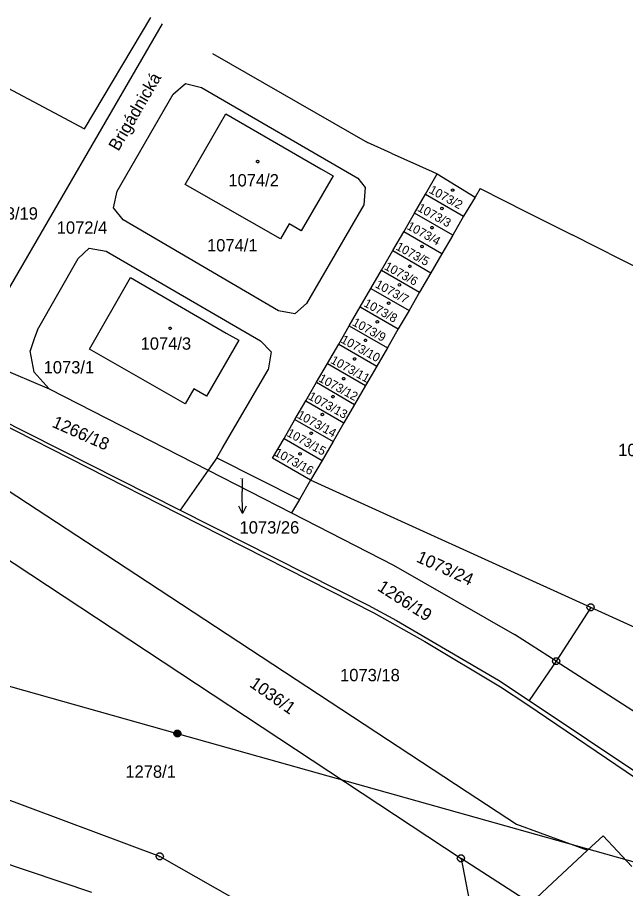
# Model space of a CAD drawing. Extents: x -806774 to -803680, y -1151731 to -1150053.
# Drawn here: x -804287.8 to -804204.1, y -1150483.9 to -1150364 of the extents above; entities that cross this region are included whole.
import ezdxf

# ---------------------------------------------------------------- set-up
doc = ezdxf.new("R2010")
doc.units = 0
for name, color, linetype in [('1', 7, 'Continuous'), ('12', 7, 'Continuous'), ('2', 7, 'Continuous'), ('5', 7, 'Continuous'), ('6', 7, 'Continuous'), ('7', 7, 'Continuous'), ('8', 7, 'Continuous')]:
    doc.layers.add(name, color=color, linetype=linetype)

msp = doc.modelspace()

# ---------------------------------------------------------------- linework, layer by layer
at = {"layer": '1'}
for p, q in [((-804290.87, -1150404.61), (-804267.79, -1150364.83)), ((-804278.54, -1150379.3), (-804269.42, -1150363.95)), ((-804298.27, -1150368.8), (-804278.54, -1150379.3)), ((-804260.94, -1150368.94), (-804239.57, -1150381.18)), ((-804266.34, -1150374.52), (-804264.66, -1150373.06)), ((-804264.66, -1150373.06), (-804262.44, -1150373.59)), ((-804262.44, -1150373.59), (-804240.91, -1150386.08)), ((-804274.06, -1150387.9), (-804266.34, -1150374.52)), ((-804264.71, -1150386.94), (-804259.1, -1150377.21)), ((-804259.1, -1150377.21), (-804246, -1150384.78)), ((-804236.34, -1150382.63), (-804239.57, -1150381.18)), ((-804236.34, -1150382.63), (-804230.68, -1150385.18)), ((-804246, -1150384.78), (-804244.3, -1150385.76)), ((-804230.68, -1150385.18), (-804230.02, -1150385.47)), ((-804244.3, -1150385.76), (-804248.7, -1150393.35)), ((-804240.91, -1150386.08), (-804239.91, -1150387.38)), ((-804231.6, -1150388.3), (-804230.02, -1150385.47)), ((-804230.02, -1150385.47), (-804224.77, -1150388.7)), ((-804251.58, -1150394.44), (-804264.71, -1150386.94)), ((-804239.91, -1150387.38), (-804240.1, -1150389.76)), ((-804224.07, -1150387.51), (-804224.77, -1150388.7)), ((-804224.07, -1150387.51), (-804217.74, -1150390.71)), ((-804274.55, -1150390.16), (-804274.06, -1150387.9)), ((-804233.1, -1150390.9), (-804231.6, -1150388.3)), ((-804231.6, -1150388.3), (-804226.36, -1150391.34)), ((-804224.77, -1150388.7), (-804226.36, -1150391.34)), ((-804240.1, -1150389.76), (-804248.01, -1150403.37)), ((-804273.23, -1150391.84), (-804274.55, -1150390.16)), ((-804234.59, -1150393.46), (-804233.1, -1150390.9)), ((-804227.86, -1150393.94), (-804233.1, -1150390.9)), ((-804217.74, -1150390.71), (-804211.44, -1150393.91)), ((-804251.86, -1150404.36), (-804273.23, -1150391.84)), ((-804250.38, -1150392.37), (-804251.58, -1150394.44)), ((-804248.7, -1150393.35), (-804250.38, -1150392.37)), ((-804226.36, -1150391.34), (-804227.86, -1150393.94)), ((-804236.1, -1150396.07), (-804234.59, -1150393.46)), ((-804229.34, -1150396.5), (-804234.59, -1150393.46)), ((-804227.86, -1150393.94), (-804229.34, -1150396.5)), ((-804193.78, -1150402.81), (-804211.44, -1150393.91)), ((-804279.4, -1150397.15), (-804277.88, -1150395.72)), ((-804277.88, -1150395.72), (-804275.56, -1150396.16)), ((-804237.66, -1150398.76), (-804236.1, -1150396.07)), ((-804236.1, -1150396.07), (-804230.86, -1150399.11)), ((-804285.02, -1150406.97), (-804279.4, -1150397.15)), ((-804275.56, -1150396.16), (-804254.32, -1150408.51)), ((-804229.34, -1150396.5), (-804230.86, -1150399.11)), ((-804239.11, -1150401.26), (-804237.66, -1150398.76)), ((-804237.66, -1150398.76), (-804232.42, -1150401.8)), ((-804230.86, -1150399.11), (-804232.42, -1150401.8)), ((-804277.84, -1150409.62), (-804272.2, -1150399.78)), ((-804272.2, -1150399.78), (-804259.06, -1150407.42)), ((-804240.59, -1150403.81), (-804239.11, -1150401.26)), ((-804239.11, -1150401.26), (-804233.87, -1150404.3)), ((-804232.42, -1150401.8), (-804233.87, -1150404.3)), ((-804249.6, -1150404.77), (-804251.86, -1150404.36)), ((-804248.01, -1150403.37), (-804249.6, -1150404.77)), ((-804242.1, -1150406.41), (-804240.59, -1150403.81)), ((-804240.59, -1150403.81), (-804235.35, -1150406.85)), ((-804233.87, -1150404.3), (-804235.35, -1150406.85)), ((-804243.56, -1150408.94), (-804242.1, -1150406.41)), ((-804242.1, -1150406.41), (-804236.85, -1150409.45)), ((-804235.35, -1150406.85), (-804236.85, -1150409.45)), ((-804285.02, -1150406.97), (-804285.45, -1150408.22)), ((-804259.06, -1150407.42), (-804257.31, -1150408.41)), ((-804285.45, -1150408.22), (-804286.03, -1150409.89)), ((-804257.31, -1150408.41), (-804261.75, -1150416.09)), ((-804254.32, -1150408.51), (-804252.87, -1150409.99)), ((-804245.11, -1150411.61), (-804243.56, -1150408.94)), ((-804243.56, -1150408.94), (-804238.32, -1150411.98)), ((-804285.45, -1150412.79), (-804286.03, -1150409.89)), ((-804264.67, -1150417.17), (-804277.84, -1150409.62)), ((-804252.87, -1150409.99), (-804253.25, -1150412.49)), ((-804236.85, -1150409.45), (-804238.32, -1150411.98)), ((-804246.61, -1150414.2), (-804245.11, -1150411.61)), ((-804245.11, -1150411.61), (-804239.87, -1150414.65)), ((-804291.43, -1150411.7), (-804283.39, -1150415.1)), ((-804283.39, -1150415.1), (-804285.45, -1150412.79)), ((-804259.59, -1150423.33), (-804253.25, -1150412.49)), ((-804238.32, -1150411.98), (-804239.87, -1150414.65)), ((-804283.39, -1150415.1), (-804261.52, -1150426.31)), ((-804263.48, -1150415.09), (-804264.67, -1150417.17)), ((-804261.75, -1150416.09), (-804263.48, -1150415.09)), ((-804248.08, -1150416.74), (-804246.61, -1150414.2)), ((-804246.61, -1150414.2), (-804241.37, -1150417.24)), ((-804239.87, -1150414.65), (-804241.37, -1150417.24)), ((-804294.74, -1150417.47), (-804265.66, -1150432.25)), ((-804294.48, -1150417.09), (-804265.36, -1150431.82)), ((-804249.58, -1150419.32), (-804248.08, -1150416.74)), ((-804248.08, -1150416.74), (-804242.84, -1150419.78)), ((-804241.37, -1150417.24), (-804242.84, -1150419.78)), ((-804251.08, -1150421.93), (-804249.58, -1150419.32)), ((-804249.58, -1150419.32), (-804244.34, -1150422.36)), ((-804242.84, -1150419.78), (-804244.34, -1150422.36)), ((-804252.65, -1150424.64), (-804251.08, -1150421.93)), ((-804251.08, -1150421.93), (-804245.85, -1150424.97)), ((-804244.34, -1150422.36), (-804245.85, -1150424.97)), ((-804298.67, -1150422.8), (-804271.5, -1150440.64)), ((-804260.34, -1150424.61), (-804259.59, -1150423.33)), ((-804260.34, -1150424.61), (-804261.52, -1150426.31)), ((-804260.34, -1150424.61), (-804248.96, -1150430.34)), ((-804247.42, -1150427.68), (-804252.65, -1150424.64)), ((-804245.85, -1150424.97), (-804247.42, -1150427.68)), ((-804261.52, -1150426.31), (-804265.36, -1150431.82)), ((-804261.52, -1150426.31), (-804250.04, -1150432.2)), ((-804247.42, -1150427.68), (-804248.96, -1150430.34)), ((-804208.87, -1150445.2), (-804247.42, -1150427.68)), ((-804301, -1150430.74), (-804226.72, -1150479.76)), ((-804248.96, -1150430.34), (-804250.04, -1150432.2)), ((-804265.36, -1150431.82), (-804239.5, -1150444.89)), ((-804265.66, -1150432.25), (-804238.71, -1150445.94)), ((-804250.04, -1150432.2), (-804236.02, -1150439.39)), ((-804236.02, -1150439.39), (-804219.37, -1150448.94)), ((-804271.5, -1150440.64), (-804225.88, -1150470.58)), ((-804239.5, -1150444.89), (-804235.62, -1150446.99)), ((-804208.87, -1150445.2), (-804213.63, -1150452.62)), ((-804163.83, -1150465.67), (-804208.87, -1150445.2)), ((-804238.71, -1150445.94), (-804231.71, -1150449.89)), ((-804235.62, -1150446.99), (-804221.57, -1150455.2)), ((-804231.71, -1150449.89), (-804221.27, -1150456.12)), ((-804213.63, -1150452.62), (-804219.37, -1150448.94)), ((-804213.63, -1150452.62), (-804217.33, -1150458.04)), ((-804213.63, -1150452.62), (-804176.02, -1150476.77)), ((-804221.57, -1150455.2), (-804217.33, -1150458.04)), ((-804221.27, -1150456.12), (-804217.68, -1150458.55)), ((-804217.33, -1150458.04), (-804188.61, -1150477.27)), ((-804217.68, -1150458.55), (-804183.31, -1150481.83)), ((-804268.19, -1150479.5), (-804301.77, -1150466.98)), ((-804225.88, -1150470.58), (-804219.07, -1150475.05)), ((-804219.07, -1150475.05), (-804209.3, -1150478.65)), ((-804207.15, -1150476.64), (-804209.3, -1150478.65)), ((-804207.15, -1150476.64), (-804203.22, -1150480.89)), ((-804209.3, -1150478.65), (-804211.42, -1150480.62)), ((-804240.65, -1150495.11), (-804268.19, -1150479.5)), ((-804215.71, -1150486.85), (-804226.72, -1150479.76)), ((-804226.72, -1150479.76), (-804221.47, -1150507.06)), ((-804211.42, -1150480.62), (-804214.82, -1150483.78)), ((-804214.82, -1150483.78), (-804216.44, -1150485.29))]:
    msp.add_line(p, q, dxfattribs=at)
at = {"layer": '12'}
for p, q in [((-804264.71, -1150386.94), (-804259.1, -1150377.21)), ((-804259.1, -1150377.21), (-804246, -1150384.78)), ((-804246, -1150384.78), (-804244.3, -1150385.76)), ((-804244.3, -1150385.76), (-804248.7, -1150393.35)), ((-804231.6, -1150388.3), (-804230.02, -1150385.47)), ((-804230.02, -1150385.47), (-804224.77, -1150388.7)), ((-804251.58, -1150394.44), (-804264.71, -1150386.94)), ((-804233.1, -1150390.9), (-804231.6, -1150388.3)), ((-804231.6, -1150388.3), (-804226.36, -1150391.34)), ((-804231.6, -1150388.3), (-804226.36, -1150391.34)), ((-804224.77, -1150388.7), (-804226.36, -1150391.34)), ((-804234.59, -1150393.46), (-804233.1, -1150390.9)), ((-804227.86, -1150393.94), (-804233.1, -1150390.9)), ((-804227.86, -1150393.94), (-804233.1, -1150390.9)), ((-804250.38, -1150392.37), (-804251.58, -1150394.44)), ((-804248.7, -1150393.35), (-804250.38, -1150392.37)), ((-804226.36, -1150391.34), (-804227.86, -1150393.94)), ((-804236.1, -1150396.07), (-804234.59, -1150393.46)), ((-804229.34, -1150396.5), (-804234.59, -1150393.46)), ((-804229.34, -1150396.5), (-804234.59, -1150393.46)), ((-804227.86, -1150393.94), (-804229.34, -1150396.5)), ((-804237.66, -1150398.76), (-804236.1, -1150396.07)), ((-804236.1, -1150396.07), (-804230.86, -1150399.11)), ((-804236.1, -1150396.07), (-804230.86, -1150399.11)), ((-804229.34, -1150396.5), (-804230.86, -1150399.11)), ((-804239.11, -1150401.26), (-804237.66, -1150398.76)), ((-804237.66, -1150398.76), (-804232.42, -1150401.8)), ((-804237.66, -1150398.76), (-804232.42, -1150401.8)), ((-804230.86, -1150399.11), (-804232.42, -1150401.8)), ((-804277.84, -1150409.62), (-804272.2, -1150399.78)), ((-804272.2, -1150399.78), (-804259.06, -1150407.42)), ((-804240.59, -1150403.81), (-804239.11, -1150401.26)), ((-804239.11, -1150401.26), (-804233.87, -1150404.3)), ((-804239.11, -1150401.26), (-804233.87, -1150404.3)), ((-804232.42, -1150401.8), (-804233.87, -1150404.3)), ((-804242.1, -1150406.41), (-804240.59, -1150403.81)), ((-804240.59, -1150403.81), (-804235.35, -1150406.85)), ((-804240.59, -1150403.81), (-804235.35, -1150406.85)), ((-804233.87, -1150404.3), (-804235.35, -1150406.85)), ((-804243.56, -1150408.94), (-804242.1, -1150406.41)), ((-804242.1, -1150406.41), (-804236.85, -1150409.45)), ((-804242.1, -1150406.41), (-804236.85, -1150409.45)), ((-804235.35, -1150406.85), (-804236.85, -1150409.45)), ((-804259.06, -1150407.42), (-804257.31, -1150408.41)), ((-804257.31, -1150408.41), (-804261.75, -1150416.09)), ((-804245.11, -1150411.61), (-804243.56, -1150408.94)), ((-804243.56, -1150408.94), (-804238.32, -1150411.98)), ((-804243.56, -1150408.94), (-804238.32, -1150411.98)), ((-804264.67, -1150417.17), (-804277.84, -1150409.62)), ((-804236.85, -1150409.45), (-804238.32, -1150411.98)), ((-804246.61, -1150414.2), (-804245.11, -1150411.61)), ((-804245.11, -1150411.61), (-804239.87, -1150414.65)), ((-804245.11, -1150411.61), (-804239.87, -1150414.65)), ((-804238.32, -1150411.98), (-804239.87, -1150414.65)), ((-804263.48, -1150415.09), (-804264.67, -1150417.17)), ((-804261.75, -1150416.09), (-804263.48, -1150415.09)), ((-804248.08, -1150416.74), (-804246.61, -1150414.2)), ((-804246.61, -1150414.2), (-804241.37, -1150417.24)), ((-804246.61, -1150414.2), (-804241.37, -1150417.24)), ((-804239.87, -1150414.65), (-804241.37, -1150417.24)), ((-804249.58, -1150419.32), (-804248.08, -1150416.74)), ((-804248.08, -1150416.74), (-804242.84, -1150419.78)), ((-804248.08, -1150416.74), (-804242.84, -1150419.78)), ((-804241.37, -1150417.24), (-804242.84, -1150419.78)), ((-804251.08, -1150421.93), (-804249.58, -1150419.32)), ((-804249.58, -1150419.32), (-804244.34, -1150422.36)), ((-804249.58, -1150419.32), (-804244.34, -1150422.36)), ((-804242.84, -1150419.78), (-804244.34, -1150422.36)), ((-804252.65, -1150424.64), (-804251.08, -1150421.93)), ((-804251.08, -1150421.93), (-804245.85, -1150424.97)), ((-804251.08, -1150421.93), (-804245.85, -1150424.97)), ((-804244.34, -1150422.36), (-804245.85, -1150424.97)), ((-804247.42, -1150427.68), (-804252.65, -1150424.64)), ((-804245.85, -1150424.97), (-804247.42, -1150427.68)), ((-804207.15, -1150476.64), (-804209.3, -1150478.65)), ((-804207.15, -1150476.64), (-804203.22, -1150480.89)), ((-804209.3, -1150478.65), (-804211.42, -1150480.62)), ((-804211.42, -1150480.62), (-804214.82, -1150483.78)), ((-804214.82, -1150483.78), (-804216.44, -1150485.29))]:
    msp.add_line(p, q, dxfattribs=at)
at = {"layer": '5'}
for points in [[(-804254.71, -1150383.63), (-804254.61, -1150383.65), (-804254.56, -1150383.74), (-804254.54, -1150383.8), (-804254.56, -1150383.89), (-804254.64, -1150383.96), (-804254.71, -1150383.97), (-804254.8, -1150383.94), (-804254.86, -1150383.88), (-804254.88, -1150383.8), (-804254.86, -1150383.71), (-804254.78, -1150383.64)], [(-804227.79, -1150387.58), (-804227.71, -1150387.65), (-804227.71, -1150387.75), (-804227.72, -1150387.81), (-804227.78, -1150387.88), (-804227.89, -1150387.9), (-804227.95, -1150387.88), (-804228.02, -1150387.81), (-804228.04, -1150387.73), (-804228.02, -1150387.65), (-804227.96, -1150387.58), (-804227.85, -1150387.56)], [(-804229.27, -1150390.12), (-804229.19, -1150390.19), (-804229.19, -1150390.29), (-804229.2, -1150390.35), (-804229.26, -1150390.42), (-804229.37, -1150390.44), (-804229.43, -1150390.42), (-804229.5, -1150390.35), (-804229.52, -1150390.27), (-804229.5, -1150390.19), (-804229.44, -1150390.12), (-804229.33, -1150390.1)], [(-804230.63, -1150392.75), (-804230.55, -1150392.82), (-804230.55, -1150392.92), (-804230.56, -1150392.98), (-804230.62, -1150393.05), (-804230.73, -1150393.07), (-804230.79, -1150393.05), (-804230.86, -1150392.98), (-804230.88, -1150392.9), (-804230.86, -1150392.82), (-804230.8, -1150392.75), (-804230.69, -1150392.73)], [(-804232, -1150395.34), (-804231.92, -1150395.41), (-804231.92, -1150395.51), (-804231.93, -1150395.57), (-804231.99, -1150395.64), (-804232.1, -1150395.66), (-804232.16, -1150395.64), (-804232.23, -1150395.57), (-804232.25, -1150395.49), (-804232.23, -1150395.41), (-804232.17, -1150395.34), (-804232.06, -1150395.32)], [(-804233.69, -1150398.08), (-804233.61, -1150398.15), (-804233.61, -1150398.25), (-804233.62, -1150398.31), (-804233.68, -1150398.38), (-804233.79, -1150398.4), (-804233.85, -1150398.38), (-804233.92, -1150398.31), (-804233.94, -1150398.23), (-804233.92, -1150398.15), (-804233.86, -1150398.08), (-804233.75, -1150398.06)], [(-804235.11, -1150400.62), (-804235.03, -1150400.69), (-804235.03, -1150400.79), (-804235.04, -1150400.85), (-804235.1, -1150400.92), (-804235.21, -1150400.94), (-804235.27, -1150400.92), (-804235.34, -1150400.85), (-804235.36, -1150400.77), (-804235.34, -1150400.69), (-804235.28, -1150400.62), (-804235.17, -1150400.6)], [(-804236.59, -1150403.16), (-804236.51, -1150403.23), (-804236.51, -1150403.33), (-804236.52, -1150403.39), (-804236.58, -1150403.46), (-804236.69, -1150403.48), (-804236.75, -1150403.46), (-804236.82, -1150403.39), (-804236.84, -1150403.31), (-804236.82, -1150403.23), (-804236.76, -1150403.16), (-804236.65, -1150403.14)], [(-804266.75, -1150406.59), (-804266.65, -1150406.61), (-804266.6, -1150406.7), (-804266.58, -1150406.76), (-804266.6, -1150406.85), (-804266.68, -1150406.92), (-804266.75, -1150406.93), (-804266.84, -1150406.9), (-804266.9, -1150406.84), (-804266.92, -1150406.76), (-804266.9, -1150406.67), (-804266.82, -1150406.6)], [(-804238.17, -1150405.72), (-804238.09, -1150405.79), (-804238.09, -1150405.89), (-804238.1, -1150405.95), (-804238.16, -1150406.02), (-804238.27, -1150406.04), (-804238.33, -1150406.02), (-804238.4, -1150405.95), (-804238.42, -1150405.87), (-804238.4, -1150405.79), (-804238.34, -1150405.72), (-804238.23, -1150405.7)], [(-804239.79, -1150408.27), (-804239.71, -1150408.34), (-804239.71, -1150408.44), (-804239.72, -1150408.5), (-804239.78, -1150408.57), (-804239.89, -1150408.59), (-804239.95, -1150408.57), (-804240.02, -1150408.5), (-804240.04, -1150408.42), (-804240.02, -1150408.34), (-804239.96, -1150408.27), (-804239.85, -1150408.25)], [(-804241.3, -1150410.84), (-804241.22, -1150410.91), (-804241.22, -1150411.01), (-804241.23, -1150411.07), (-804241.29, -1150411.14), (-804241.4, -1150411.16), (-804241.46, -1150411.14), (-804241.53, -1150411.07), (-804241.55, -1150410.99), (-804241.53, -1150410.91), (-804241.47, -1150410.84), (-804241.36, -1150410.82)], [(-804242.8, -1150413.54), (-804242.72, -1150413.61), (-804242.72, -1150413.71), (-804242.73, -1150413.77), (-804242.79, -1150413.84), (-804242.9, -1150413.86), (-804242.96, -1150413.84), (-804243.03, -1150413.77), (-804243.05, -1150413.69), (-804243.03, -1150413.61), (-804242.97, -1150413.54), (-804242.86, -1150413.52)], [(-804244.28, -1150416.02), (-804244.2, -1150416.09), (-804244.2, -1150416.19), (-804244.21, -1150416.25), (-804244.27, -1150416.32), (-804244.38, -1150416.34), (-804244.44, -1150416.32), (-804244.51, -1150416.25), (-804244.53, -1150416.17), (-804244.51, -1150416.09), (-804244.45, -1150416.02), (-804244.34, -1150416)], [(-804245.73, -1150418.48), (-804245.65, -1150418.55), (-804245.65, -1150418.65), (-804245.66, -1150418.71), (-804245.72, -1150418.78), (-804245.83, -1150418.8), (-804245.89, -1150418.78), (-804245.96, -1150418.71), (-804245.98, -1150418.63), (-804245.96, -1150418.55), (-804245.9, -1150418.48), (-804245.79, -1150418.46)], [(-804247.26, -1150421.07), (-804247.18, -1150421.14), (-804247.18, -1150421.24), (-804247.19, -1150421.3), (-804247.25, -1150421.37), (-804247.36, -1150421.39), (-804247.42, -1150421.37), (-804247.49, -1150421.3), (-804247.51, -1150421.22), (-804247.49, -1150421.14), (-804247.43, -1150421.07), (-804247.32, -1150421.05)], [(-804248.79, -1150423.91), (-804248.71, -1150423.98), (-804248.71, -1150424.08), (-804248.72, -1150424.14), (-804248.78, -1150424.21), (-804248.89, -1150424.23), (-804248.95, -1150424.21), (-804249.02, -1150424.14), (-804249.04, -1150424.06), (-804249.02, -1150423.98), (-804248.96, -1150423.91), (-804248.85, -1150423.89)]]:
    msp.add_lwpolyline(points, close=True, dxfattribs=at)
at = {"layer": '6'}
for p, q in [((-804314.68, -1150448.75), (-804265.77, -1150462.58)), ((-804265.77, -1150462.58), (-804195.07, -1150482.47)), ((-804292.47, -1150479.43), (-804277.59, -1150484.41))]:
    msp.add_line(p, q, dxfattribs=at)
msp.add_lwpolyline([(-804265.92, -1150462.1), (-804265.61, -1150462.1), (-804265.36, -1150462.28), (-804265.26, -1150462.57), (-804265.36, -1150462.86), (-804265.61, -1150463.04), (-804265.92, -1150463.04), (-804266.17, -1150462.86), (-804266.27, -1150462.57), (-804266.17, -1150462.28), (-804265.92, -1150462.1), (-804265.89, -1150462.14), (-804265.65, -1150462.14), (-804265.49, -1150462.22), (-804266.05, -1150462.22), (-804266.13, -1150462.3), (-804265.41, -1150462.3), (-804265.41, -1150462.38), (-804266.13, -1150462.38), (-804266.17, -1150462.46), (-804265.37, -1150462.46), (-804265.33, -1150462.54), (-804266.21, -1150462.54), (-804266.21, -1150462.62), (-804265.33, -1150462.62), (-804265.36, -1150462.7), (-804266.17, -1150462.7), (-804266.16, -1150462.78), (-804265.35, -1150462.78), (-804265.4, -1150462.86), (-804266.12, -1150462.86), (-804266.04, -1150462.94), (-804265.48, -1150462.94), (-804265.59, -1150463.02), (-804265.93, -1150463.02)], dxfattribs=at)
at = {"layer": '7'}
for p in [(-804256.86, -1150427.5), (-804256.78, -1150432.26)]:
    msp.add_line(p, (-804256.83, -1150429.26), dxfattribs=at)
msp.add_lwpolyline([(-804256.3, -1150431.25), (-804256.78, -1150432.26), (-804257.3, -1150431.27)], dxfattribs=at)
at = {"layer": '8'}
for p, q in [((-804208.99, -1150445.2), (-804208.75, -1150445.2)), ((-804213.75, -1150452.62), (-804213.51, -1150452.62)), ((-804268.31, -1150479.5), (-804268.07, -1150479.5)), ((-804226.84, -1150479.76), (-804226.6, -1150479.76))]:
    msp.add_line(p, q, dxfattribs=at)
for points in [[(-804208.72, -1150444.72), (-804208.47, -1150444.9), (-804208.37, -1150445.19), (-804208.47, -1150445.48), (-804208.72, -1150445.66), (-804209.03, -1150445.66), (-804209.28, -1150445.48), (-804209.38, -1150445.19), (-804209.28, -1150444.9), (-804209.03, -1150444.72)], [(-804213.48, -1150452.14), (-804213.23, -1150452.32), (-804213.13, -1150452.61), (-804213.23, -1150452.9), (-804213.48, -1150453.08), (-804213.79, -1150453.08), (-804214.04, -1150452.9), (-804214.14, -1150452.61), (-804214.04, -1150452.32), (-804213.79, -1150452.14)], [(-804268.04, -1150479.02), (-804267.79, -1150479.2), (-804267.69, -1150479.49), (-804267.79, -1150479.78), (-804268.04, -1150479.96), (-804268.35, -1150479.96), (-804268.6, -1150479.78), (-804268.7, -1150479.49), (-804268.6, -1150479.2), (-804268.35, -1150479.02)], [(-804226.57, -1150479.28), (-804226.32, -1150479.46), (-804226.22, -1150479.75), (-804226.32, -1150480.04), (-804226.57, -1150480.22), (-804226.88, -1150480.22), (-804227.13, -1150480.04), (-804227.23, -1150479.75), (-804227.13, -1150479.46), (-804226.88, -1150479.28)]]:
    msp.add_lwpolyline(points, close=True, dxfattribs=at)

# ---------------------------------------------------------------- texts
at = {"layer": '2'}
for s, height, p in [('1074/2', 1.7, (-804258.74, -1150387.23)), ('1073/19', 1.7, (-804293.17, -1150391.8)), ('1072/4', 1.7, (-804282.36, -1150393.74)), ('1074/1', 1.7, (-804261.68, -1150396.18)), ('1074/3', 1.7, (-804270.82, -1150409.71)), ('1073/1', 1.7, (-804284.17, -1150412.98)), ('1073/17', 1.7, (-804205.08, -1150424.37)), ('1073/26', 0.1, (-804257.13, -1150427.5)), ('1073/18', 1.7, (-804243.36, -1150455.37)), ('1278/1', 1.7, (-804272.92, -1150468.67))]:
    msp.add_text(s, height=height, dxfattribs=at).set_placement(p)
for s, height, rotation, p in [('1073/2', 1.2, 331.2269, (-804231.22, -1150388.05)), ('1073/3', 1.2, 331.2269, (-804232.82, -1150390.53)), ('1073/4', 1.2, 331.2269, (-804234.28, -1150393.04)), ('1073/5', 1.2, 331.2269, (-804235.8, -1150395.86)), ('1073/6', 1.2, 331.2269, (-804237.38, -1150398.58)), ('1073/7', 1.2, 331.2269, (-804238.64, -1150401.06)), ('1073/8', 1.2, 331.2269, (-804240.21, -1150403.67)), ('1073/9', 1.2, 331.2269, (-804241.79, -1150406.29)), ('1073/10', 1.2, 331.2269, (-804243.36, -1150408.67)), ('1073/11', 1.2, 331.2269, (-804244.77, -1150411.5)), ('1073/12', 1.2, 331.2269, (-804246.43, -1150414.01)), ('1073/13', 1.2, 331.2269, (-804247.85, -1150416.47)), ('1073/14', 1.2, 331.2269, (-804249.39, -1150419.04)), ('1266/18', 1.7, 336.1543, (-804283.13, -1150420.3)), ('1073/15', 1.2, 331.2269, (-804250.81, -1150421.54)), ('1073/16', 1.2, 331.2269, (-804252.52, -1150424.23)), ('1073/24', 1.7, 335.696, (-804232.99, -1150438.87)), ('1266/19', 1.7, 327.4454, (-804238.36, -1150442.77)), ('1036/1', 1.7, 324.9244, (-804255.95, -1150456.03))]:
    msp.add_text(s, height=height, rotation=rotation, dxfattribs=at).set_placement(p)
at = {"layer": '7'}
msp.add_text('Brigádnická', height=1.7, rotation=59.8168, dxfattribs=at).set_placement((-804273.88, -1150382.47))
msp.add_text('1073/26', height=1.7, dxfattribs=at).set_placement((-804257.2, -1150435.03))

doc.saveas('drawing.dxf')
